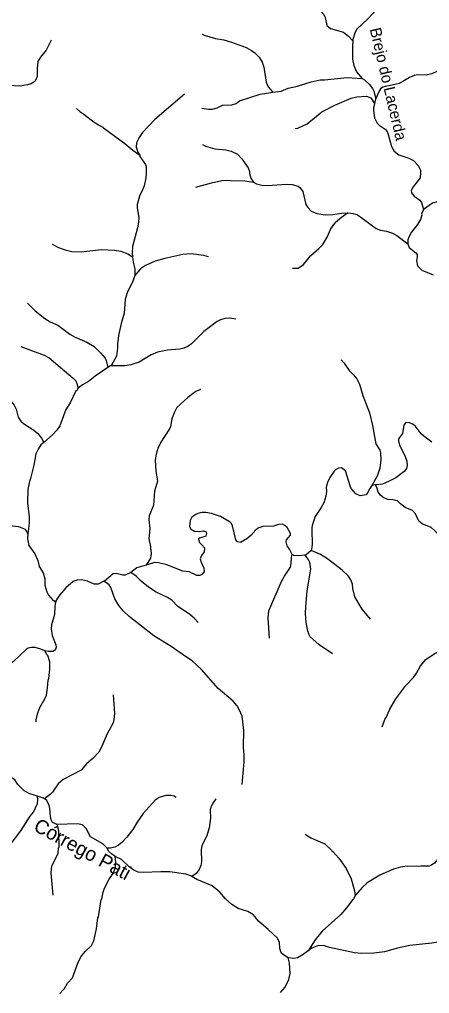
# Model space of a CAD drawing. Extents: x 280.4 to 335.6, y 8893.9 to 8949.5.
# Drawn here: x 304.07 to 309.86, y 8894.06 to 8907.81 of the extents above; entities that cross this region are included whole.
import ezdxf
from ezdxf.enums import TextEntityAlignment as Align

# ---------------------------------------------------------------- set-up
doc = ezdxf.new("R2010")
doc.units = 0
doc.header["$LTSCALE"] = 0.064
doc.layers.add('61', color=7, linetype='Continuous')
doc.layers.add('7', color=7, linetype='Continuous', lineweight=25)

msp = doc.modelspace()

# ---------------------------------------------------------------- linework, layer by layer
at = {"layer": '7'}
for p, q in [((309.0991, 8906.6845), (309.0863, 8906.6233)), ((305.3592, 8902.9195), (305.3224, 8902.8949)), ((309.0992, 8901.2385), (309.0492, 8901.2321))]:
    msp.add_line(p, q, dxfattribs=at)
for points in [[(306.459, 8908.9497), (306.5285, 8908.9233), (306.5319, 8908.9165), (306.8052, 8908.7547), (306.9552, 8908.647), (307.1689, 8908.4784), (307.397, 8908.376), (307.4782, 8908.3542), (307.6657, 8908.3199), (307.9329, 8908.2293), (308.0871, 8908.2065), (308.1367, 8908.1889), (308.1929, 8908.1345), (308.2914, 8907.9722), (308.3689, 8907.8813), (308.3882, 8907.8418), (308.4132, 8907.7272), (308.4647, 8907.6838), (308.6475, 8907.632), (308.7206, 8907.5778), (308.7814, 8907.5098)], [(309.2186, 8908.4753), (309.198, 8908.4444), (309.1519, 8908.3867), (309.1237, 8908.3291), (309.1458, 8908.1266), (309.1345, 8908.0412), (309.1199, 8907.9837), (309.0669, 8907.9006), (308.9891, 8907.8181), (308.835, 8907.6767), (308.8121, 8907.633), (308.7815, 8907.5305), (308.7814, 8907.5098)], [(306.6525, 8907.6032), (306.6808, 8907.5891), (306.843, 8907.5431), (306.958, 8907.5236), (307.0677, 8907.4918), (307.2754, 8907.4146), (307.3514, 8907.375), (307.3974, 8907.34), (307.4575, 8907.28), (307.4999, 8907.2109), (307.5242, 8907.1399), (307.5572, 8906.9259), (307.5863, 8906.8591), (307.6483, 8906.7839)], [(304.5235, 8907.518), (304.4496, 8907.3779), (304.3721, 8907.2801), (304.3325, 8907.2173), (304.3225, 8907.1214), (304.3224, 8907.0062), (304.2948, 8906.9418), (304.2382, 8906.9051), (304.1894, 8906.8867), (304.0851, 8906.8713), (303.9252, 8906.8806)], [(308.7814, 8907.5098), (308.7812, 8907.488), (308.7733, 8907.4526), (308.7764, 8907.2494), (308.7943, 8907.1616), (308.8333, 8907.0721), (308.9133, 8906.9804)], [(310.2749, 8907.3713), (310.2211, 8907.3069), (310.1034, 8907.1859), (310.029, 8907.1199), (309.9678, 8907.0776), (309.8965, 8907.0448), (309.8143, 8907.0264), (309.696, 8907.0279), (309.6442, 8907.0197), (309.5777, 8906.9943), (309.5114, 8906.9493), (309.4331, 8906.9094), (309.3338, 8906.8823), (309.2379, 8906.867), (309.2034, 8906.8536), (309.1728, 8906.8331), (309.1542, 8906.811), (309.0991, 8906.6845)], [(307.6483, 8906.7839), (307.7666, 8906.8006), (307.8668, 8906.84), (307.9991, 8906.8685), (308.1895, 8906.932), (308.3167, 8906.9591), (308.3822, 8906.9609), (308.7012, 8906.9943), (308.9133, 8906.9804)], [(308.9133, 8906.9804), (308.9441, 8906.9601), (309.0083, 8906.9), (309.0562, 8906.8392), (309.0783, 8906.8005), (309.0993, 8906.709), (309.0991, 8906.6845)], [(306.4048, 8906.7557), (305.985, 8906.4012), (305.8102, 8906.2141), (305.7651, 8906.1465), (305.7278, 8906.07), (305.7203, 8906.0084), (305.7441, 8905.936), (305.7717, 8905.8942)], [(306.6479, 8906.5598), (306.747, 8906.5434), (306.7988, 8906.5435), (306.8627, 8906.5629), (306.9414, 8906.6005), (307.0739, 8906.606), (307.1348, 8906.6248), (307.182, 8906.6632), (307.473, 8906.7592), (307.6483, 8906.7839)], [(307.9661, 8906.272), (308.0017, 8906.275), (308.1339, 8906.3395), (308.3405, 8906.5053), (308.5279, 8906.6037), (308.7575, 8906.6997), (308.8363, 8906.7178), (308.9706, 8906.7271), (309.0359, 8906.7043), (309.0863, 8906.6233)], [(309.0863, 8906.6233), (309.0739, 8906.564), (309.0723, 8906.5251), (309.0837, 8906.4205), (309.124, 8906.3475), (309.1496, 8906.3208), (309.2358, 8906.2615), (309.2626, 8906.2293), (309.28, 8906.1867), (309.3279, 8906.0179), (309.364, 8905.9522), (309.4289, 8905.9013), (309.5696, 8905.8535), (309.6377, 8905.8193), (309.7046, 8905.751), (309.7342, 8905.6845), (309.7374, 8905.6543), (309.7309, 8905.5743), (309.6332, 8905.4473), (309.6021, 8905.3959), (309.6063, 8905.3644), (309.647, 8905.3164), (309.7257, 8905.2611), (309.7477, 8905.2287), (309.7757, 8905.1296)], [(304.8786, 8906.5543), (304.9264, 8906.5119), (304.9845, 8906.4746), (305.1275, 8906.3606), (305.1882, 8906.3216), (305.2526, 8906.2908), (305.2597, 8906.2801), (305.5617, 8906.0598), (305.6739, 8905.9661), (305.7717, 8905.8942)], [(306.6585, 8906.0446), (306.6981, 8906.0222), (306.8314, 8905.9841), (306.9868, 8905.9707), (307.0646, 8905.9533), (307.1536, 8905.9081), (307.2127, 8905.8455), (307.3015, 8905.7171), (307.3223, 8905.6652), (307.3206, 8905.6389), (307.3419, 8905.5712), (307.3779, 8905.5158)], [(305.7717, 8905.8942), (305.7744, 8905.8758), (305.8544, 8905.7645), (305.8626, 8905.7309), (305.8641, 8905.6374), (305.8574, 8905.5743), (305.8321, 8905.4607), (305.8115, 8905.4038), (305.7664, 8905.316), (305.7331, 8905.2009), (305.7347, 8905.1519), (305.757, 8905.0161), (305.7554, 8904.9514), (305.7398, 8904.8673), (305.6692, 8904.6066), (305.6628, 8904.5219), (305.6701, 8904.4593)], [(306.5648, 8905.4415), (306.7847, 8905.5068), (306.9307, 8905.539), (307.0115, 8905.543), (307.0548, 8905.5359), (307.2538, 8905.5327), (307.3779, 8905.5158)], [(307.3779, 8905.5158), (307.422, 8905.4896), (307.4955, 8905.4739), (307.5746, 8905.4671), (307.8448, 8905.4861), (307.9239, 8905.4808), (308.0087, 8905.4573), (308.0358, 8905.435), (308.0735, 8905.3834), (308.1186, 8905.1969), (308.1443, 8905.1554), (308.1927, 8905.1025), (308.2734, 8905.0719), (308.3871, 8905.0545), (308.4997, 8905.0589), (308.619, 8905.0769), (308.7052, 8905.0818)], [(311.272, 8905.5461), (311.2431, 8905.494), (311.1903, 8905.4468), (311.1561, 8905.428), (311.0138, 8905.3903), (310.9462, 8905.3522), (310.8807, 8905.2904), (310.8309, 8905.2235), (310.7649, 8905.1526), (310.7197, 8905.1193), (310.658, 8905.0928), (310.5876, 8905.0898), (310.5197, 8905.1067), (310.3261, 8905.2176), (310.1853, 8905.2607), (310.1143, 8905.2654), (310.0446, 8905.2575), (309.9055, 8905.2166), (309.7757, 8905.1296)], [(309.7757, 8905.1296), (309.7494, 8905.0618), (309.7526, 8905.0469), (309.7351, 8904.9858), (309.6927, 8904.9169), (309.6076, 8904.8076), (309.5697, 8904.7378), (309.5584, 8904.7018), (309.5544, 8904.6434)], [(307.9261, 8904.2976), (308.0079, 8904.3015), (308.0816, 8904.3518), (308.1862, 8904.4771), (308.3006, 8904.5755), (308.3552, 8904.6356), (308.4159, 8904.7382), (308.4694, 8904.8561), (308.5253, 8904.9353), (308.5317, 8904.937), (308.534, 8904.9474), (308.621, 8905.0214), (308.7052, 8905.0818)], [(308.7052, 8905.0818), (308.7123, 8905.0822), (308.785, 8905.0734), (308.8419, 8905.056), (309.1092, 8904.8602), (309.1682, 8904.8386), (309.2562, 8904.8237), (309.3416, 8904.7951), (309.3991, 8904.7614), (309.5544, 8904.6434)], [(304.5366, 8904.6407), (304.6238, 8904.5906), (304.7178, 8904.5576), (304.8144, 8904.535), (304.9469, 8904.5284), (305.2308, 8904.5619), (305.4147, 8904.5522), (305.5031, 8904.5401), (305.6025, 8904.5038), (305.6701, 8904.4593)], [(309.5544, 8904.6434), (309.5754, 8904.5932), (309.6676, 8904.5181), (309.6861, 8904.4916), (309.6896, 8904.4659), (309.6805, 8904.4062), (309.6947, 8904.3332), (309.7534, 8904.2732), (309.9135, 8904.2036)], [(305.6701, 8904.4593), (305.6787, 8904.386), (305.7009, 8904.2907), (305.7038, 8904.1972)], [(306.7419, 8904.4607), (306.6746, 8904.48), (306.493, 8904.5026), (306.3786, 8904.4923), (306.128, 8904.4367), (305.9889, 8904.3987), (305.8509, 8904.338), (305.7811, 8904.2884), (305.7038, 8904.1972)], [(305.7038, 8904.1972), (305.6721, 8904.1157), (305.5941, 8903.9517), (305.5638, 8903.8564), (305.5507, 8903.6631), (305.5093, 8903.5199), (305.4713, 8903.3492), (305.458, 8903.2313), (305.4578, 8903.1722), (305.4412, 8903.0571), (305.3726, 8902.9285), (305.3592, 8902.9195)], [(304.1855, 8903.8037), (304.2954, 8903.6952), (304.43, 8903.5888), (304.5074, 8903.5419), (304.6154, 8903.4924), (304.7835, 8903.3663), (304.8595, 8903.3267), (305.0267, 8903.2566), (305.1264, 8903.1949), (305.2176, 8903.1053), (305.2812, 8903.0263), (305.2964, 8902.996), (305.3224, 8902.8949)], [(307.1295, 8903.5802), (307.0413, 8903.5943), (306.9779, 8903.5879), (306.9132, 8903.5703), (306.8633, 8903.5484), (306.6782, 8903.4056), (306.5025, 8903.2303), (306.4511, 8903.193), (306.3958, 8903.1677), (306.3368, 8903.1561), (306.1633, 8903.1415), (306.0225, 8903.1118), (305.9346, 8903.0746), (305.7625, 8902.9726), (305.6466, 8902.9339), (305.561, 8902.9211), (305.3592, 8902.9195)], [(303.6087, 8903.4422), (303.6222, 8903.3994), (303.7231, 8903.2571), (303.7628, 8903.1795), (303.7755, 8903.0307), (303.7483, 8902.8276), (303.7438, 8902.7427), (303.7513, 8902.7306), (303.7676, 8902.6557), (303.795, 8902.6006), (303.8739, 8902.4998), (303.945, 8902.4301), (303.9981, 8902.3671), (304.0268, 8902.3094), (304.0571, 8902.1951), (304.0946, 8902.138), (304.1285, 8902.1059), (304.2777, 8902.011), (304.3336, 8901.9647), (304.3851, 8901.9001), (304.4165, 8901.8377)], [(304.0914, 8903.1953), (304.4229, 8903.0709), (304.4925, 8903.0343), (304.834, 8902.7452), (304.8678, 8902.7065), (304.885, 8902.6724), (304.9, 8902.6066)], [(305.3224, 8902.8949), (305.1439, 8902.7751), (305.0491, 8902.6992), (304.9647, 8902.6535), (304.9, 8902.6066)], [(308.6173, 8903.0056), (308.6588, 8902.9573), (308.7297, 8902.8529), (308.7884, 8902.7943), (308.8345, 8902.7368), (308.8728, 8902.6637), (308.9207, 8902.5013), (309.0145, 8902.2564), (309.0594, 8902.0798), (309.104, 8901.8204), (309.1594, 8901.7296), (309.1712, 8901.6935), (309.1766, 8901.5949), (309.1606, 8901.4738), (309.1246, 8901.3601), (309.0492, 8901.2321)], [(304.9, 8902.6066), (304.8846, 8902.5735), (304.8709, 8902.5668), (304.789, 8902.3959), (304.7278, 8902.3021), (304.6427, 8902.0722), (304.6033, 8902.012), (304.5416, 8901.9473), (304.4165, 8901.8377)], [(306.6299, 8902.5965), (306.6181, 8902.5822), (306.5647, 8902.558), (306.4527, 8902.4748), (306.2956, 8902.3313), (306.2576, 8902.2573), (306.2259, 8902.1732), (306.2035, 8902.062), (306.1907, 8902.0293), (306.0595, 8901.8298), (306.0566, 8901.8079), (306.0334, 8901.7658), (306.0028, 8901.6738), (305.989, 8901.5936), (306.0003, 8901.4312), (306.024, 8901.2927), (305.9819, 8901.1488), (305.9666, 8900.9546), (305.9068, 8900.8038), (305.8978, 8900.7435), (305.9122, 8900.6243), (305.8995, 8900.4768), (305.9215, 8900.3636), (305.9219, 8900.3325), (305.928, 8900.3262), (305.9345, 8900.2537), (305.9269, 8900.2438), (305.9214, 8900.2058), (305.8623, 8900.1072)], [(309.8958, 8901.8439), (309.7805, 8901.9275), (309.7451, 8901.9606), (309.6587, 8902.0752), (309.6243, 8902.0981), (309.5815, 8902.1163), (309.5277, 8902.1223), (309.5011, 8902.0831), (309.483, 8901.963), (309.4265, 8901.8872), (309.4242, 8901.863), (309.4399, 8901.8022), (309.5158, 8901.6561), (309.5435, 8901.5729), (309.5456, 8901.5138), (309.5356, 8901.47), (309.5023, 8901.4258), (309.3875, 8901.3402), (309.2934, 8901.29), (309.1995, 8901.2513), (309.0992, 8901.2385)], [(304.4165, 8901.8377), (304.3769, 8901.803), (304.3353, 8901.744), (304.3057, 8901.6772), (304.2775, 8901.5194), (304.2314, 8901.329), (304.2135, 8901.2892), (304.1923, 8901.1785), (304.185, 8900.9852), (304.2104, 8900.786), (304.2105, 8900.6965), (304.1934, 8900.5495)], [(309.0492, 8901.2321), (309.0177, 8901.1865), (308.9881, 8901.1254), (308.9688, 8901.1002), (308.8837, 8901.0831), (308.8245, 8901.1104), (308.7574, 8901.1875), (308.749, 8901.2127), (308.7417, 8901.2165), (308.7439, 8901.2268), (308.6758, 8901.4397), (308.6192, 8901.4813), (308.5788, 8901.4773), (308.5366, 8901.4513), (308.5158, 8901.4305), (308.4566, 8901.3442), (308.4227, 8901.2731), (308.4054, 8901.2091), (308.4069, 8901.1466), (308.3972, 8901.0812), (308.3708, 8900.9875), (308.3346, 8900.9214), (308.2474, 8900.7915), (308.2059, 8900.6645), (308.2008, 8900.6298), (308.2006, 8900.5918), (308.2066, 8900.4103), (308.2032, 8900.35), (308.1912, 8900.3137)], [(302.886, 8901.2024), (302.9351, 8901.1984), (303.0167, 8901.1764), (303.0597, 8901.1549), (303.2685, 8900.9864), (303.391, 8900.9112), (303.6412, 8900.8244), (303.8059, 8900.7198), (303.8776, 8900.6871), (303.9731, 8900.6631), (304.0577, 8900.6531), (304.1533, 8900.6141), (304.1934, 8900.5495)], [(310.1207, 8900.4791), (310.0064, 8900.5161), (309.9304, 8900.5994), (309.887, 8900.6352), (309.7568, 8900.6881), (309.7116, 8900.7244), (309.6623, 8900.8292), (309.6234, 8900.8777), (309.5164, 8900.9176), (309.4519, 8900.9694), (309.4104, 8901.0117), (309.3449, 8901.029), (309.2738, 8901.0325), (309.2074, 8901.0624), (309.1704, 8901.0943), (309.1396, 8901.1351), (309.1219, 8901.1876), (309.0992, 8901.2385)], [(307.8393, 8900.4326), (307.8458, 8900.4616), (307.9013, 8900.5287), (307.9014, 8900.5509), (307.8515, 8900.6378), (307.821, 8900.6664), (307.788, 8900.6831), (307.7305, 8900.6777), (307.662, 8900.6578), (307.5079, 8900.649), (307.4524, 8900.6323), (307.4123, 8900.6021), (307.3408, 8900.5259), (307.2843, 8900.4774), (307.1922, 8900.4267), (307.1506, 8900.4342), (307.126, 8900.4622), (307.0795, 8900.6629), (307.066, 8900.6953), (307.047, 8900.7127), (306.9104, 8900.7906), (306.7852, 8900.8371), (306.7069, 8900.8483), (306.6478, 8900.8468), (306.5902, 8900.834), (306.5615, 8900.8212), (306.5093, 8900.7817), (306.4818, 8900.7354), (306.4719, 8900.655), (306.4904, 8900.6181), (306.5458, 8900.5863), (306.6102, 8900.5799), (306.6709, 8900.5891), (306.7083, 8900.5763), (306.7162, 8900.551), (306.7043, 8900.5171), (306.6134, 8900.4871), (306.5999, 8900.4759), (306.6096, 8900.428), (306.6491, 8900.3946), (306.6879, 8900.3503), (306.6795, 8900.2942), (306.6415, 8900.2407), (306.6257, 8900.196), (306.6383, 8900.1481), (306.6744, 8900.0632), (306.6792, 8900.0117), (306.6495, 8899.9725), (306.619, 8899.9594), (306.5784, 8899.9579), (306.4686, 8900.0103), (306.3796, 8900.0193), (306.152, 8900.1095), (306.0384, 8900.138), (305.9786, 8900.1414), (305.8623, 8900.1072)], [(304.1934, 8900.5495), (304.1851, 8900.4782), (304.1859, 8900.4749), (304.2074, 8900.3847), (304.2888, 8900.2635), (304.3338, 8900.1728), (304.3532, 8900.0865), (304.4074, 8899.9968), (304.4309, 8899.9118), (304.4335, 8899.8206), (304.4577, 8899.7292), (304.4844, 8899.6838), (304.5517, 8899.6086), (304.5634, 8899.606), (304.5802, 8899.5778)], [(307.9238, 8900.2538), (307.8852, 8900.3324), (307.8549, 8900.3792), (307.8393, 8900.4326)], [(308.1912, 8900.3137), (308.1206, 8900.253), (308.1051, 8900.2472)], [(309.0308, 8899.345), (309.0052, 8899.3689), (308.914, 8899.4859), (308.8088, 8899.6596), (308.7814, 8899.7762), (308.7743, 8899.8393), (308.7536, 8899.899), (308.7177, 8899.9491), (308.6279, 8900.0339), (308.4236, 8900.1939), (308.3238, 8900.2543), (308.1912, 8900.3137)], [(307.6035, 8899.0746), (307.5851, 8899.3637), (307.5932, 8899.4609), (307.7666, 8899.8667), (307.8136, 8899.9512), (307.8983, 8900.0776), (307.9112, 8900.1294), (307.9132, 8900.2197), (307.9238, 8900.2538)], [(308.1051, 8900.2472), (308.0976, 8900.2444), (308.0182, 8900.236), (307.9439, 8900.2413), (307.9238, 8900.2538)], [(308.4907, 8898.852), (308.3051, 8898.9797), (308.1744, 8899.0969), (308.1448, 8899.1724), (308.1191, 8899.2979), (308.1128, 8899.4234), (308.116, 8899.5218), (308.1367, 8899.7442), (308.1862, 8900.0496), (308.1799, 8900.1191), (308.1705, 8900.1536), (308.1506, 8900.1901), (308.1051, 8900.2472)], [(305.6448, 8900.0039), (305.6344, 8899.9961), (305.5681, 8899.9645), (305.5333, 8899.9628), (305.4387, 8899.9879), (305.3946, 8899.9849), (305.2734, 8899.8814), (305.2648, 8899.8772)], [(305.8623, 8900.1072), (305.7314, 8900.0686), (305.6448, 8900.0039)], [(306.5951, 8899.2966), (306.547, 8899.3531), (306.4749, 8899.4137), (306.3084, 8899.5205), (306.2237, 8899.6104), (306.1648, 8899.6482), (306.0034, 8899.7258), (305.8946, 8899.7946), (305.7942, 8899.8756), (305.7218, 8899.9496), (305.6448, 8900.0039)], [(305.2648, 8899.8772), (305.1834, 8899.8374), (305.1271, 8899.8348), (305.0325, 8899.8776), (304.9505, 8899.8964), (304.8871, 8899.8933), (304.8304, 8899.874), (304.7259, 8899.7836), (304.6413, 8899.6879), (304.6011, 8899.624), (304.5802, 8899.5778)], [(307.2153, 8897.0086), (307.2459, 8897.3301), (307.2459, 8897.4221), (307.2348, 8897.5364), (307.2394, 8897.7699), (307.217, 8897.9706), (307.1819, 8898.0561), (307.1455, 8898.1194), (307.0896, 8898.1851), (306.8806, 8898.3653), (306.6435, 8898.6329), (306.5118, 8898.7534), (306.4153, 8898.8146), (306.217, 8898.9554), (305.9725, 8899.1094), (305.6237, 8899.3824), (305.5353, 8899.4597), (305.4742, 8899.5348), (305.4178, 8899.6302), (305.3622, 8899.7922), (305.3415, 8899.8289), (305.2648, 8899.8772)], [(304.5802, 8899.5778), (304.5709, 8899.5257), (304.566, 8899.4088), (304.5258, 8899.2626), (304.5208, 8899.2043), (304.5348, 8899.1132), (304.5868, 8898.9807), (304.59, 8898.9471), (304.5832, 8898.9205), (304.5669, 8898.8991), (304.543, 8898.8864), (304.4849, 8898.8863), (304.434, 8898.8963)], [(304.434, 8898.8963), (304.3756, 8898.9197), (304.2937, 8898.9405), (304.2425, 8898.9437), (304.1953, 8898.9311), (304.1679, 8898.9138), (303.9892, 8898.7466), (303.9414, 8898.711), (303.92, 8898.7019)], [(309.195, 8897.8199), (309.2389, 8897.9471), (309.2482, 8897.9544), (309.3024, 8898.0715), (309.3866, 8898.2164), (309.5301, 8898.4052), (309.6345, 8898.5211), (309.6767, 8898.5791), (309.7335, 8898.6818), (309.8117, 8898.7712), (309.9263, 8898.8525), (310.0414, 8898.9085), (310.1367, 8898.9467), (310.1753, 8898.9753), (310.2165, 8898.9957)], [(304.3114, 8897.8907), (304.3099, 8897.9212), (304.3338, 8898.0177), (304.3604, 8898.0932), (304.4308, 8898.2154), (304.4537, 8898.2695), (304.4712, 8898.3702), (304.4796, 8898.48), (304.4888, 8898.5047), (304.5016, 8898.6389), (304.5016, 8898.7396), (304.4737, 8898.828), (304.4581, 8898.8438), (304.434, 8898.8963)], [(305.3957, 8898.2724), (305.4163, 8898.0088), (305.4063, 8897.9235), (305.3941, 8897.8809), (305.3128, 8897.7241), (305.2283, 8897.5234), (305.1928, 8897.4651), (305.1115, 8897.377), (305.0209, 8897.2976), (304.9424, 8897.2113), (304.6897, 8897.0772), (304.6184, 8897.0166), (304.541, 8896.8993), (304.5105, 8896.8689), (304.4278, 8896.8059)], [(304.3263, 8896.8448), (304.2218, 8896.8781), (304.138, 8896.9206), (304.0512, 8897.0065), (304.0065, 8897.0715), (303.9412, 8897.1161), (303.8705, 8897.1538), (303.6859, 8897.2285), (303.6156, 8897.2667), (303.5516, 8897.3139), (303.5041, 8897.333), (303.3965, 8897.3205), (303.2635, 8897.3375), (303.1846, 8897.366), (303.0695, 8897.4263), (302.9455, 8897.4593), (302.8879, 8897.4551), (302.841, 8897.4394)], [(303.6948, 8895.4756), (303.7083, 8895.503), (303.7227, 8895.5683), (303.7243, 8895.6193), (303.7179, 8895.6318), (303.7263, 8895.7251), (303.8041, 8895.9515), (303.8811, 8896.0778), (304.0937, 8896.3513), (304.2266, 8896.5592), (304.2725, 8896.6193), (304.3286, 8896.7371), (304.3319, 8896.7934), (304.3263, 8896.8448)], [(304.4278, 8896.8059), (304.4152, 8896.8164), (304.3263, 8896.8448)], [(306.2849, 8896.8239), (306.2562, 8896.8439), (306.2064, 8896.8518), (306.1418, 8896.8518), (306.0438, 8896.8232), (305.9877, 8896.7861), (305.8182, 8896.5966), (305.7371, 8896.4774), (305.675, 8896.3728), (305.5885, 8896.2628), (305.5193, 8896.1903), (305.4733, 8896.1522), (305.4211, 8896.1236), (305.36, 8896.1076), (305.3135, 8896.1088)], [(304.6043, 8896.4434), (304.5412, 8896.4707), (304.5222, 8896.5088), (304.5099, 8896.5617), (304.5016, 8896.6679), (304.4922, 8896.7121), (304.4591, 8896.7797), (304.4278, 8896.8059)], [(306.8466, 8896.8068), (306.8047, 8896.7431), (306.7916, 8896.7118), (306.7808, 8896.7045), (306.7658, 8896.6453), (306.7692, 8896.5322), (306.753, 8896.3978), (306.72, 8896.2808), (306.6498, 8896.1476), (306.6382, 8896.0873), (306.6446, 8895.921), (306.633, 8895.8641), (306.6095, 8895.8076), (306.5705, 8895.7529), (306.505, 8895.7097)], [(304.5474, 8895.4448), (304.5208, 8895.7563), (304.524, 8895.8228), (304.5369, 8895.8683), (304.6026, 8895.9937), (304.6185, 8896.0385), (304.6264, 8896.1119), (304.6326, 8896.1245), (304.6295, 8896.3498), (304.621, 8896.3975), (304.6043, 8896.4434)], [(305.3135, 8896.1088), (305.2522, 8896.1695), (305.0754, 8896.2704), (305.0168, 8896.3842), (304.962, 8896.4375), (304.8943, 8896.4536), (304.6043, 8896.4434)], [(308.1051, 8896.3065), (308.1886, 8896.2551), (308.3824, 8896.1676), (308.4798, 8896.0796), (308.4818, 8896.0705), (308.4977, 8896.0623), (308.5824, 8895.9693), (308.6856, 8895.8197), (308.7553, 8895.677), (308.805, 8895.5076), (308.8132, 8895.4362)], [(305.4254, 8895.9918), (305.3721, 8896.0266), (305.332, 8896.0664), (305.3135, 8896.1088)], [(310.4425, 8896.1158), (310.2596, 8896.1194), (310.1756, 8896.1059), (310.0659, 8896.0475), (309.9736, 8895.9501), (309.933, 8895.8976), (309.881, 8895.862), (309.8586, 8895.8556), (309.7387, 8895.8562), (309.7048, 8895.8492), (309.5456, 8895.8523), (309.4505, 8895.8397), (309.3537, 8895.8123), (309.1625, 8895.7296), (308.9812, 8895.6172), (308.9113, 8895.5553), (308.8192, 8895.4471), (308.8132, 8895.4362)], [(304.6443, 8894.0559), (304.6848, 8894.1013), (304.7096, 8894.1291), (304.7516, 8894.2024), (304.8212, 8894.2758), (304.8953, 8894.4838), (304.9422, 8894.5749), (305.0022, 8894.6497), (305.0896, 8894.734), (305.1234, 8894.7979), (305.1601, 8894.9689), (305.1799, 8895.123), (305.1876, 8895.1397), (305.2291, 8895.3856), (305.2356, 8895.3926), (305.2554, 8895.4869), (305.276, 8895.5427), (305.3413, 8895.67), (305.3971, 8895.7516), (305.4282, 8895.8338), (305.4323, 8895.9131), (305.4254, 8895.9918)], [(306.505, 8895.7097), (306.5018, 8895.7115), (306.4207, 8895.7403), (306.1968, 8895.7755), (306.0688, 8895.7755), (305.8201, 8895.7627), (305.7498, 8895.7691), (305.6867, 8895.7964), (305.6222, 8895.8471), (305.5124, 8895.9489), (305.4254, 8895.9918)], [(307.8668, 8894.5593), (307.8025, 8894.6), (307.769, 8894.6309), (307.7514, 8894.6913), (307.7447, 8894.7776), (307.7156, 8894.8357), (307.5862, 8894.962), (307.4478, 8895.0781), (307.3755, 8895.1693), (307.298, 8895.2138), (307.1593, 8895.2588), (307.0731, 8895.3108), (306.981, 8895.393), (306.904, 8895.4888), (306.7933, 8895.5756), (306.5782, 8895.6682), (306.505, 8895.7097)], [(308.8132, 8895.4362), (308.7889, 8895.3922), (308.7777, 8895.3849), (308.6928, 8895.2664), (308.612, 8895.1729), (308.3447, 8894.9375), (308.2467, 8894.8149), (308.1509, 8894.661)], [(310.4826, 8894.7629), (310.3421, 8894.8175), (310.242, 8894.8305), (310.1196, 8894.8083), (310.0957, 8894.8093), (310.0349, 8894.7908), (309.8969, 8894.768), (309.5865, 8894.7325), (309.4087, 8894.6953), (309.2284, 8894.6448), (309.0754, 8894.6242), (308.9013, 8894.621), (308.8045, 8894.6309), (308.4493, 8894.7071), (308.3789, 8894.731), (308.2967, 8894.7342), (308.2016, 8894.6955), (308.1509, 8894.661)], [(308.1509, 8894.661), (308.0791, 8894.6071), (307.9975, 8894.5618), (307.9551, 8894.5507), (307.8668, 8894.5593)], [(307.7577, 8894.0726), (307.7921, 8894.1092), (307.8254, 8894.1446), (307.8744, 8894.253), (307.8949, 8894.3379), (307.8857, 8894.4826), (307.8668, 8894.5593)]]:
    msp.add_lwpolyline(points, dxfattribs=at)

# ---------------------------------------------------------------- texts
at = {"layer": '61'}
for s, height, rotation, p in [('Brejo do Lacerda', 0.16, 283.241, (309.204, 8906.8828)), ('Córrego Pati', 0.2, 331.532, (304.9167, 8896.0075))]:
    msp.add_text(s, height=height, rotation=rotation, dxfattribs=at).set_placement(p, align=Align.CENTER)

doc.saveas('drawing.dxf')
